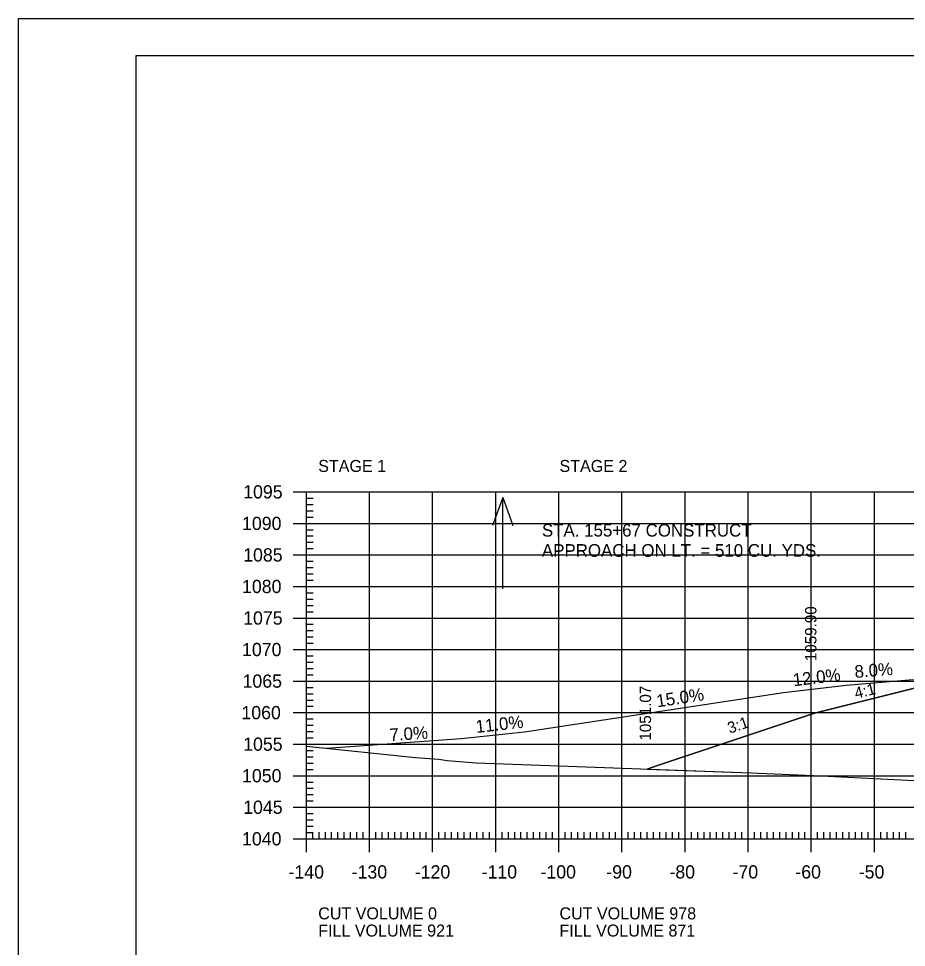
# Model space of a CAD drawing. Extents: x 1322838 to 1324533, y 339903 to 351025.
# Drawn here: x 1323450 to 1323590.7, y 344996.9 to 345144.2 of the extents above; entities that cross this region are included whole.
import ezdxf

# ---------------------------------------------------------------- set-up
doc = ezdxf.new("R2010")
doc.units = 0
for name, color, linetype in [('R_Axis', 7, 'Continuous'), ('R_Axis Annot', 7, 'Continuous'), ('R_Border', 7, 'Continuous'), ('R_Border Notes', 7, 'Continuous'), ('R_Drive', 7, 'Continuous'), ('R_Exist Surface', 7, 'Continuous'), ('R_Fin Surface', 7, 'Continuous'), ('R_Grid', 7, 'Continuous'), ('R_No Plot', 7, 'Continuous'), ('R_Water Annot', 7, 'Continuous'), ('R_Xsect Elev', 7, 'Continuous'), ('R_Xsect Slope', 7, 'Continuous')]:
    doc.layers.add(name, color=color, linetype=linetype)

msp = doc.modelspace()

# ---------------------------------------------------------------- linework, layer by layer
at = {"layer": 'R_Axis'}
for p, q in [((1323493.48, 345069.14), (1323497.68, 345069.14)), ((1323495.58, 345014.14), (1323495.58, 345069.14)), ((1323495.58, 345068.14), (1323496.63, 345068.14)), ((1323495.58, 345067.14), (1323496.63, 345067.14)), ((1323495.58, 345066.14), (1323496.63, 345066.14)), ((1323495.58, 345065.14), (1323496.63, 345065.14)), ((1323493.48, 345064.14), (1323497.68, 345064.14)), ((1323495.58, 345063.14), (1323496.63, 345063.14)), ((1323495.58, 345062.14), (1323496.63, 345062.14)), ((1323495.58, 345061.14), (1323496.63, 345061.14)), ((1323495.58, 345060.14), (1323496.63, 345060.14)), ((1323493.48, 345059.14), (1323497.68, 345059.14)), ((1323495.58, 345058.14), (1323496.63, 345058.14)), ((1323495.58, 345057.14), (1323496.63, 345057.14)), ((1323495.58, 345056.14), (1323496.63, 345056.14)), ((1323493.48, 345054.14), (1323497.68, 345054.14)), ((1323495.58, 345055.14), (1323496.63, 345055.14)), ((1323495.58, 345053.14), (1323496.63, 345053.14)), ((1323495.58, 345052.14), (1323496.63, 345052.14)), ((1323495.58, 345051.14), (1323496.63, 345051.14)), ((1323495.58, 345050.14), (1323496.63, 345050.14)), ((1323493.48, 345049.14), (1323497.68, 345049.14)), ((1323495.58, 345048.14), (1323496.63, 345048.14)), ((1323495.58, 345047.14), (1323496.63, 345047.14)), ((1323495.58, 345046.14), (1323496.63, 345046.14)), ((1323493.48, 345044.14), (1323497.68, 345044.14)), ((1323495.58, 345045.14), (1323496.63, 345045.14)), ((1323495.58, 345043.14), (1323496.63, 345043.14)), ((1323495.58, 345042.14), (1323496.63, 345042.14)), ((1323495.58, 345041.14), (1323496.63, 345041.14)), ((1323495.58, 345040.14), (1323496.63, 345040.14)), ((1323493.48, 345039.14), (1323497.68, 345039.14)), ((1323495.58, 345038.14), (1323496.63, 345038.14)), ((1323495.58, 345037.14), (1323496.63, 345037.14)), ((1323495.58, 345036.14), (1323496.63, 345036.14)), ((1323495.58, 345035.14), (1323496.63, 345035.14)), ((1323493.48, 345034.14), (1323497.68, 345034.14)), ((1323495.58, 345033.14), (1323496.63, 345033.14)), ((1323495.58, 345032.14), (1323496.63, 345032.14)), ((1323495.58, 345031.14), (1323496.63, 345031.14)), ((1323493.48, 345029.14), (1323497.68, 345029.14)), ((1323495.58, 345030.14), (1323496.63, 345030.14)), ((1323495.58, 345028.14), (1323496.63, 345028.14)), ((1323495.58, 345027.14), (1323496.63, 345027.14)), ((1323495.58, 345026.14), (1323496.63, 345026.14)), ((1323495.58, 345025.14), (1323496.63, 345025.14)), ((1323493.48, 345024.14), (1323497.68, 345024.14)), ((1323495.58, 345023.14), (1323496.63, 345023.14)), ((1323495.58, 345022.14), (1323496.63, 345022.14)), ((1323495.58, 345021.14), (1323496.63, 345021.14)), ((1323493.48, 345019.14), (1323497.68, 345019.14)), ((1323495.58, 345020.14), (1323496.63, 345020.14)), ((1323495.58, 345018.14), (1323496.63, 345018.14)), ((1323495.58, 345017.14), (1323496.63, 345017.14)), ((1323495.58, 345012.04), (1323495.58, 345016.24)), ((1323495.58, 345016.14), (1323496.63, 345016.14)), ((1323505.58, 345012.04), (1323505.58, 345016.24)), ((1323515.58, 345012.04), (1323515.58, 345016.24)), ((1323525.58, 345012.04), (1323525.58, 345016.24)), ((1323535.58, 345012.04), (1323535.58, 345016.24)), ((1323545.58, 345012.04), (1323545.58, 345016.24)), ((1323555.58, 345012.04), (1323555.58, 345016.24)), ((1323565.58, 345012.04), (1323565.58, 345016.24)), ((1323575.58, 345012.04), (1323575.58, 345016.24)), ((1323585.58, 345012.04), (1323585.58, 345016.24)), ((1323495.58, 345015.14), (1323496.63, 345015.14)), ((1323496.58, 345014.14), (1323496.58, 345015.19)), ((1323497.58, 345014.14), (1323497.58, 345015.19)), ((1323498.58, 345014.14), (1323498.58, 345015.19)), ((1323499.58, 345014.14), (1323499.58, 345015.19)), ((1323500.58, 345014.14), (1323500.58, 345015.19)), ((1323501.58, 345014.14), (1323501.58, 345015.19)), ((1323502.58, 345014.14), (1323502.58, 345015.19)), ((1323503.58, 345014.14), (1323503.58, 345015.19)), ((1323504.58, 345014.14), (1323504.58, 345015.19)), ((1323506.58, 345014.14), (1323506.58, 345015.19)), ((1323507.58, 345014.14), (1323507.58, 345015.19)), ((1323508.58, 345014.14), (1323508.58, 345015.19)), ((1323509.58, 345014.14), (1323509.58, 345015.19)), ((1323510.58, 345014.14), (1323510.58, 345015.19)), ((1323511.58, 345014.14), (1323511.58, 345015.19)), ((1323512.58, 345014.14), (1323512.58, 345015.19)), ((1323513.58, 345014.14), (1323513.58, 345015.19)), ((1323514.58, 345014.14), (1323514.58, 345015.19)), ((1323516.58, 345014.14), (1323516.58, 345015.19)), ((1323517.58, 345014.14), (1323517.58, 345015.19)), ((1323518.58, 345014.14), (1323518.58, 345015.19)), ((1323519.58, 345014.14), (1323519.58, 345015.19)), ((1323520.58, 345014.14), (1323520.58, 345015.19)), ((1323521.58, 345014.14), (1323521.58, 345015.19)), ((1323522.58, 345014.14), (1323522.58, 345015.19)), ((1323523.58, 345014.14), (1323523.58, 345015.19)), ((1323524.58, 345014.14), (1323524.58, 345015.19)), ((1323526.58, 345014.14), (1323526.58, 345015.19)), ((1323527.58, 345014.14), (1323527.58, 345015.19)), ((1323528.58, 345014.14), (1323528.58, 345015.19)), ((1323529.58, 345014.14), (1323529.58, 345015.19)), ((1323530.58, 345014.14), (1323530.58, 345015.19)), ((1323531.58, 345014.14), (1323531.58, 345015.19)), ((1323532.58, 345014.14), (1323532.58, 345015.19)), ((1323533.58, 345014.14), (1323533.58, 345015.19)), ((1323534.58, 345014.14), (1323534.58, 345015.19)), ((1323536.58, 345014.14), (1323536.58, 345015.19)), ((1323537.58, 345014.14), (1323537.58, 345015.19)), ((1323538.58, 345014.14), (1323538.58, 345015.19)), ((1323539.58, 345014.14), (1323539.58, 345015.19)), ((1323540.58, 345014.14), (1323540.58, 345015.19)), ((1323541.58, 345014.14), (1323541.58, 345015.19)), ((1323542.58, 345014.14), (1323542.58, 345015.19)), ((1323543.58, 345014.14), (1323543.58, 345015.19)), ((1323544.58, 345014.14), (1323544.58, 345015.19)), ((1323546.58, 345014.14), (1323546.58, 345015.19)), ((1323547.58, 345014.14), (1323547.58, 345015.19)), ((1323548.58, 345014.14), (1323548.58, 345015.19)), ((1323549.58, 345014.14), (1323549.58, 345015.19)), ((1323550.58, 345014.14), (1323550.58, 345015.19)), ((1323551.58, 345014.14), (1323551.58, 345015.19)), ((1323552.58, 345014.14), (1323552.58, 345015.19)), ((1323553.58, 345014.14), (1323553.58, 345015.19)), ((1323554.58, 345014.14), (1323554.58, 345015.19)), ((1323556.58, 345014.14), (1323556.58, 345015.19)), ((1323557.58, 345014.14), (1323557.58, 345015.19)), ((1323558.58, 345014.14), (1323558.58, 345015.19)), ((1323559.58, 345014.14), (1323559.58, 345015.19)), ((1323560.58, 345014.14), (1323560.58, 345015.19)), ((1323561.58, 345014.14), (1323561.58, 345015.19)), ((1323562.58, 345014.14), (1323562.58, 345015.19)), ((1323563.58, 345014.14), (1323563.58, 345015.19)), ((1323564.58, 345014.14), (1323564.58, 345015.19)), ((1323566.58, 345014.14), (1323566.58, 345015.19)), ((1323567.58, 345014.14), (1323567.58, 345015.19)), ((1323568.58, 345014.14), (1323568.58, 345015.19)), ((1323569.58, 345014.14), (1323569.58, 345015.19)), ((1323570.58, 345014.14), (1323570.58, 345015.19)), ((1323571.58, 345014.14), (1323571.58, 345015.19)), ((1323572.58, 345014.14), (1323572.58, 345015.19)), ((1323573.58, 345014.14), (1323573.58, 345015.19)), ((1323574.58, 345014.14), (1323574.58, 345015.19)), ((1323576.58, 345014.14), (1323576.58, 345015.19)), ((1323577.58, 345014.14), (1323577.58, 345015.19)), ((1323578.58, 345014.14), (1323578.58, 345015.19)), ((1323579.58, 345014.14), (1323579.58, 345015.19)), ((1323580.58, 345014.14), (1323580.58, 345015.19)), ((1323581.58, 345014.14), (1323581.58, 345015.19)), ((1323582.58, 345014.14), (1323582.58, 345015.19)), ((1323583.58, 345014.14), (1323583.58, 345015.19)), ((1323584.58, 345014.14), (1323584.58, 345015.19)), ((1323586.58, 345014.14), (1323586.58, 345015.19)), ((1323587.58, 345014.14), (1323587.58, 345015.19)), ((1323588.58, 345014.14), (1323588.58, 345015.19)), ((1323589.58, 345014.14), (1323589.58, 345015.19)), ((1323590.58, 345014.14), (1323590.58, 345015.19)), ((1323493.48, 345014.14), (1323497.68, 345014.14)), ((1323495.58, 345014.14), (1323915.58, 345014.14))]:
    msp.add_line(p, q, dxfattribs=at)
at = {"layer": 'R_Border'}
for p, q in [((1323468.58, 345138.33), (1323942.85, 345138.33)), ((1323468.58, 344830.14), (1323468.58, 345138.33))]:
    msp.add_line(p, q, dxfattribs=at)
at = {"layer": 'R_Drive'}
for p, q in [((1323530.11, 345031.06), (1323520.11, 345029.96)), ((1323520.11, 345029.96), (1323498.81, 345028.47))]:
    msp.add_line(p, q, dxfattribs=at)
msp.add_lwpolyline([(1323598.08, 345039.53), (1323591.09, 345039.26), (1323581.12, 345038.46), (1323571.19, 345037.26), (1323530.11, 345031.06)], dxfattribs=at)
at = {"layer": 'R_Exist Surface'}
msp.add_lwpolyline([(1323495.58, 345028.8), (1323512.86, 345027.03), (1323516.57, 345026.76), (1323517.87, 345026.55), (1323522.46, 345026.18), (1323565.98, 345024.61), (1323577.13, 345024.14), (1323592.99, 345023.31)], dxfattribs=at)
at = {"layer": 'R_Fin Surface'}
msp.add_lwpolyline([(1323549.59, 345025.2), (1323551.23, 345025.75), (1323576.08, 345034.03), (1323576.08, 345034.03), (1323576.09, 345034.04), (1323592.99, 345038.26)], dxfattribs=at)
at = {"layer": 'R_Grid'}
for p, q in [((1323495.58, 345069.14), (1323915.58, 345069.14)), ((1323495.58, 345014.14), (1323495.58, 345069.14)), ((1323505.58, 345014.14), (1323505.58, 345069.14)), ((1323515.58, 345014.14), (1323515.58, 345069.14)), ((1323525.58, 345014.14), (1323525.58, 345069.14)), ((1323535.58, 345014.14), (1323535.58, 345069.14)), ((1323545.58, 345014.14), (1323545.58, 345069.14)), ((1323555.58, 345014.14), (1323555.58, 345069.14)), ((1323565.58, 345014.14), (1323565.58, 345069.14)), ((1323575.58, 345014.14), (1323575.58, 345069.14)), ((1323585.58, 345014.14), (1323585.58, 345069.14)), ((1323495.58, 345064.14), (1323915.58, 345064.14)), ((1323495.58, 345059.14), (1323915.58, 345059.14)), ((1323495.58, 345054.14), (1323915.58, 345054.14)), ((1323495.58, 345049.14), (1323915.58, 345049.14)), ((1323495.58, 345044.14), (1323915.58, 345044.14)), ((1323495.58, 345039.14), (1323915.58, 345039.14)), ((1323495.58, 345034.14), (1323915.58, 345034.14)), ((1323495.58, 345029.14), (1323915.58, 345029.14)), ((1323495.58, 345024.14), (1323915.58, 345024.14)), ((1323495.58, 345019.14), (1323915.58, 345019.14)), ((1323495.58, 345014.14), (1323915.58, 345014.14))]:
    msp.add_line(p, q, dxfattribs=at)
at = {"layer": 'R_No Plot'}
msp.add_line((1323449.98, 345144.17), (1323949.98, 345144.17), dxfattribs=at)
for points in [[(1323449.97, 345144.17), (1323949.98, 345144.17), (1323949.98, 344824.16), (1323449.97, 344824.16)], [(1323819.46, 345138.33), (1323848.89, 345138.33), (1323848.89, 345123.51), (1323873.06, 345123.51), (1323907.86, 345123.51), (1323907.86, 345074.5), (1323942.67, 345074.5), (1323942.85, 344830.14), (1323468.58, 344830.14), (1323468.58, 345138.33)]]:
    msp.add_lwpolyline(points, close=True, dxfattribs=at)
msp.add_lwpolyline([(1323592.99, 345038.26), (1323576.09, 345034.04), (1323576.08, 345034.03), (1323576.08, 345034.03), (1323551.23, 345025.75), (1323549.59, 345025.2), (1323565.98, 345024.61), (1323577.13, 345024.14), (1323592.99, 345023.31)], dxfattribs=at)
at = {"layer": 'R_Water Annot'}
for p, q in [((1323526.69, 345068.24), (1323525.08, 345063.81)), ((1323526.69, 345053.76), (1323526.69, 345068.24)), ((1323526.69, 345068.24), (1323528.3, 345063.81))]:
    msp.add_line(p, q, dxfattribs=at)

# ---------------------------------------------------------------- texts
at = {"layer": 'R_Axis Annot'}
for s, height, p in [('STAGE 1', 1.904, (1323497.45, 345072.29)), ('STAGE 2', 1.904, (1323535.68, 345072.29)), ('1095', 2.1, (1323485.56, 345068.09)), ('1090', 2.1, (1323485.38, 345063.09)), ('1085', 2.1, (1323485.56, 345058.09)), ('1080', 2.1, (1323485.38, 345053.09)), ('1075', 2.1, (1323485.56, 345048.09)), ('1070', 2.1, (1323485.38, 345043.09)), ('1065', 2.1, (1323485.46, 345038.09)), ('1060', 2.1, (1323485.28, 345033.09)), ('1055', 2.1, (1323485.56, 345028.09)), ('1050', 2.1, (1323485.38, 345023.09)), ('1045', 2.1, (1323485.56, 345018.09)), ('1040', 2.1, (1323485.38, 345013.09)), ('-140', 2.1, (1323492.75, 345007.84)), ('-130', 2.1, (1323502.75, 345007.84)), ('-120', 2.1, (1323512.75, 345007.84)), ('-110', 2.1, (1323523.34, 345007.84)), ('-100', 2.1, (1323532.67, 345007.84)), ('-90', 2.1, (1323543.1, 345007.84)), ('-80', 2.1, (1323553.1, 345007.84)), ('-70', 2.1, (1323563.1, 345007.84)), ('-60', 2.1, (1323573.05, 345007.84)), ('-50', 2.1, (1323583.1, 345007.84)), ('CUT VOLUME 0', 1.9043, (1323497.45, 345001.36)), ('CUT VOLUME 978', 1.9043, (1323535.68, 345001.36)), ('FILL VOLUME 921', 1.9043, (1323497.45, 344998.64)), ('FILL VOLUME 871', 1.9043, (1323535.68, 344998.64))]:
    msp.add_text(s, height=height, dxfattribs=at).set_placement(p)
at = {"layer": 'R_Border Notes'}
for s, p in [('STA. 155+67 CONSTRUCT', (1323532.9, 345062.05)), ('APPROACH ON LT. = 510 CU. YDS.', (1323532.9, 345058.85))]:
    msp.add_text(s, height=1.9999, dxfattribs=at).set_placement(p)
at = {"layer": 'R_Drive'}
for s, rotation, p in [('12.0%', 6.8706, (1323572.78, 345038.31)), ('8.0%', 4.5806, (1323582.51, 345039.63)), ('15.0%', 8.5806, (1323551.19, 345034.97)), ('11.0%', 6.2906, (1323522.51, 345030.91)), ('7.0%', 4.0006, (1323508.82, 345029.6))]:
    msp.add_text(s, height=2, rotation=rotation, dxfattribs=at).set_placement(p)
at = {"layer": 'R_Xsect Elev'}
for s, p in [('1059.90', (1323576.39, 345042.3)), ('1051.07', (1323550.19, 345029.7))]:
    msp.add_text(s, height=1.8, rotation=90, dxfattribs=at).set_placement(p)
at = {"layer": 'R_Xsect Slope'}
for s, rotation, p in [('4:1', 14.0366, (1323582.66, 345036.31)), ('3:1', 18.4345, (1323562.65, 345030.79))]:
    msp.add_text(s, height=1.8, rotation=rotation, dxfattribs=at).set_placement(p)

doc.saveas('drawing.dxf')
